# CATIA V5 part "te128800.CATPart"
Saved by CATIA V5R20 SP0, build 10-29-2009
Part number: 1
Definition: NONE
Nomenclature: 1
Source: Unknown
Description: PART-1-DESC
Bounding box of the stored display mesh (mm): x 0 to 800, y -6 to 6, z -5.85 to 5.85
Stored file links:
  C:\Users\Utente\Desktop\IO LAVORO\3D X SITO CF\CUMSA\3D files TE\te128800.CATPart
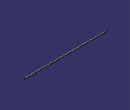
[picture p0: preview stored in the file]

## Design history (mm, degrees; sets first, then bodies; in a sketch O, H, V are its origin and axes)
Body1 "1" (main body)
  Solid1: solid without history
